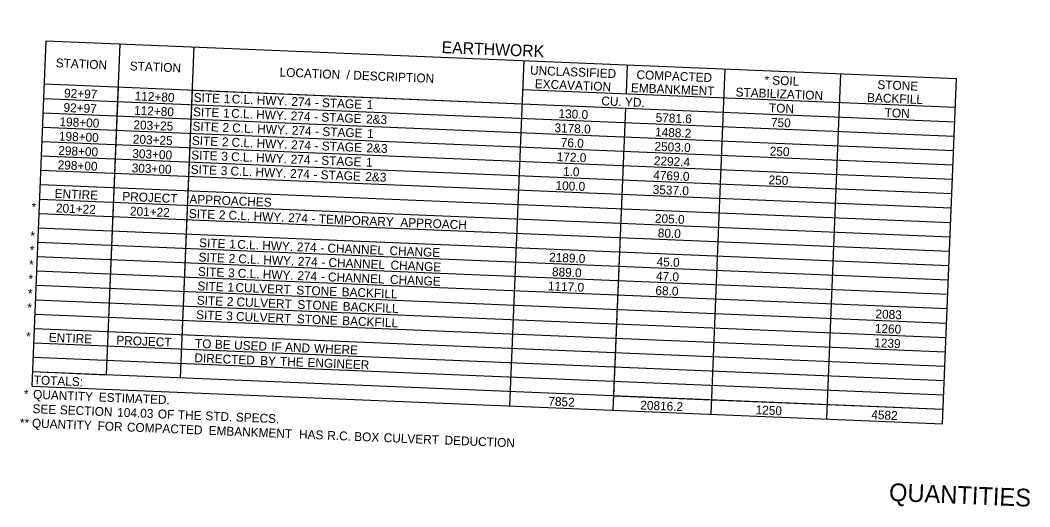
# Model space of a CAD drawing. Extents: x 1164179 to 1171425, y 1655958 to 1657208.
# Drawn here: x 1166923 to 1167607, y 1656114 to 1656443 of the extents above; entities that cross this region are included whole.
import ezdxf

# ---------------------------------------------------------------- set-up
doc = ezdxf.new("R2010")
doc.units = 0
doc.layers.add('Default', color=7, linetype='Continuous')
doc.layers.add('R_Border Prem', color=7, linetype='Continuous')

msp = doc.modelspace()

# ---------------------------------------------------------------- linework, layer by layer
at = {"layer": 'Default'}
for p, q in [((1166933.3, 1656443.19), (1166933.3, 1656443.19)), ((1166930.85, 1656195.43), (1166940.52, 1656429.23)), ((1166930.85, 1656195.43), (1166940.52, 1656429.23)), ((1166940.52, 1656429.23), (1167557.66, 1656403.7)), ((1166981.43, 1656203.09), (1166990.69, 1656427.15)), ((1167031.59, 1656201.02), (1167040.86, 1656425.08)), ((1167254.76, 1656182.03), (1167264.43, 1656415.83)), ((1167333.77, 1656393.44), (1167334.57, 1656412.93)), ((1167391.15, 1656176.39), (1167400.82, 1656410.19)), ((1167469.57, 1656173.14), (1167479.24, 1656406.94)), ((1166939.32, 1656400), (1167333.37, 1656383.7)), ((1167547.99, 1656169.9), (1167557.66, 1656403.7)), ((1166981.43, 1656203.09), (1166989.49, 1656397.93)), ((1167031.59, 1656201.02), (1167039.65, 1656395.85)), ((1167039.65, 1656395.85), (1167263.23, 1656386.6)), ((1167263.63, 1656396.34), (1167556.85, 1656384.21)), ((1166938.91, 1656390.26), (1167556.05, 1656364.73)), ((1167263.23, 1656386.6), (1167556.45, 1656374.47)), ((1166938.51, 1656380.52), (1167555.64, 1656354.99)), ((1167324.9, 1656179.13), (1167333.37, 1656383.7)), ((1167325.31, 1656188.87), (1167333.37, 1656383.7)), ((1166938.11, 1656370.78), (1167555.24, 1656345.25)), ((1166937.7, 1656361.04), (1167554.84, 1656335.51)), ((1166937.3, 1656351.29), (1167554.44, 1656325.76)), ((1166936.9, 1656341.55), (1167554.03, 1656316.02)), ((1166936.49, 1656331.81), (1167553.63, 1656306.28)), ((1166936.09, 1656322.07), (1167553.23, 1656296.54)), ((1166935.69, 1656312.33), (1167552.82, 1656286.8)), ((1166935.29, 1656302.59), (1167552.42, 1656277.06)), ((1166934.88, 1656292.84), (1167552.02, 1656267.31)), ((1166934.48, 1656283.1), (1167551.61, 1656257.57)), ((1166934.08, 1656273.36), (1167551.21, 1656247.83)), ((1166933.67, 1656263.62), (1167550.81, 1656238.09)), ((1166933.27, 1656253.88), (1167550.41, 1656228.35)), ((1166932.87, 1656244.14), (1167550, 1656218.61)), ((1166932.46, 1656234.39), (1167549.6, 1656208.86)), ((1166932.06, 1656224.65), (1167549.2, 1656199.12)), ((1166931.66, 1656214.91), (1167548.79, 1656189.38)), ((1166931.26, 1656205.17), (1166981.43, 1656203.09)), ((1166931.26, 1656205.17), (1167548.39, 1656179.64)), ((1166930.85, 1656195.43), (1167547.99, 1656169.9)), ((1167325.31, 1656188.87), (1167391.55, 1656186.13)), ((1167391.55, 1656186.13), (1167548.39, 1656179.64))]:
    msp.add_line(p, q, dxfattribs=at)

# ---------------------------------------------------------------- texts
for s, height, p in [('EARTHWORK', 8, (1167208.4, 1656420.97)), ('STATION', 6, (1166946.83, 1656411.33)), ('STATION', 6, (1166997, 1656409.25)), ('LOCATION', 6, (1167098.6, 1656405.05)), (' /', 6, (1167141.67, 1656403.27)), (' DESCRIPTION', 6, (1167146.33, 1656403.07)), ('UNCLASSIFIED', 6, (1167268.38, 1656406.36)), ('COMPACTED', 6, (1167340.53, 1656403.37)), ('EXCAVATION', 6, (1167271.62, 1656397.21)), ('EMBANKMENT', 6, (1167336.78, 1656394.52)), ('*', 6, (1167427.29, 1656399.78)), (' SOIL', 6, (1167430.37, 1656399.66)), ('STONE', 6, (1167503.84, 1656396.62)), ('92+97', 6, (1166952.48, 1656390.9)), ('112+80', 6, (1167000.33, 1656388.92)), ('SITE', 6, (1167040.3, 1656387.94)), ('STABILIZATION', 6, (1167407.73, 1656391.58)), ('BACKFILL', 6, (1167496.88, 1656387.9)), ('92+97', 6, (1166952.08, 1656381.16)), (' 1', 6, (1167058.48, 1656387.19)), (' C.L.', 6, (1167063.92, 1656386.97)), (' HWY.', 6, (1167080.87, 1656386.26)), (' 274', 6, (1167104.33, 1656385.29)), (' -', 6, (1167120.22, 1656384.64)), (' STAGE', 6, (1167125.07, 1656384.44)), (' 1', 6, (1167155.35, 1656383.18)), ('CU.', 6, (1167316.69, 1656385.59)), (' YD.', 6, (1167330.54, 1656385.02)), ('TON', 6, (1167430.36, 1656380.89)), ('112+80', 6, (1166999.93, 1656379.18)), ('SITE', 6, (1167039.9, 1656378.2)), (' 1', 6, (1167058.07, 1656377.45)), (' C.L.', 6, (1167063.51, 1656377.22)), (' HWY.', 6, (1167080.47, 1656376.52)), (' 274', 6, (1167103.93, 1656375.55)), (' STAGE', 6, (1167124.67, 1656374.69)), (' 2&3', 6, (1167154.95, 1656373.44)), ('130.0', 6, (1167287.67, 1656377.03)), ('5781.6', 6, (1167353.52, 1656374.31)), ('TON', 6, (1167508.78, 1656377.65)), ('198+00', 6, (1166949.36, 1656371.51)), ('203+25', 6, (1166999.49, 1656369.44)), ('SITE', 6, (1167039.5, 1656368.46)), (' 2', 6, (1167057.67, 1656367.71)), (' C.L.', 6, (1167064.21, 1656367.44)), (' HWY.', 6, (1167081.16, 1656366.74)), (' -', 6, (1167119.82, 1656374.9)), ('3178.0', 6, (1167284.94, 1656367.39)), ('750', 6, (1167431.68, 1656371.08)), ('198+00', 6, (1166948.95, 1656361.77)), ('203+25', 6, (1166999.09, 1656359.7)), (' 274', 6, (1167104.62, 1656365.77)), (' -', 6, (1167120.51, 1656365.11)), (' STAGE', 6, (1167125.36, 1656364.91)), (' 1', 6, (1167155.64, 1656363.65)), ('1488.2', 6, (1167353.15, 1656364.57)), ('SITE', 6, (1167039.09, 1656358.72)), (' 2', 6, (1167057.27, 1656357.97)), (' C.L.', 6, (1167063.8, 1656357.7)), (' HWY.', 6, (1167080.76, 1656356.99)), (' 274', 6, (1167104.22, 1656356.02)), (' STAGE', 6, (1167124.96, 1656355.17)), (' 2&3', 6, (1167155.24, 1656353.91)), ('76.0', 6, (1167289.19, 1656357.45)), ('2503.0', 6, (1167352.73, 1656354.83)), ('298+00', 6, (1166948.55, 1656352.03)), ('303+00', 6, (1166998.72, 1656349.95)), ('SITE', 6, (1167038.69, 1656348.98)), (' 3', 6, (1167056.86, 1656348.22)), (' C.L.', 6, (1167063.47, 1656347.95)), (' HWY.', 6, (1167080.42, 1656347.25)), (' 274', 6, (1167103.88, 1656346.28)), (' -', 6, (1167120.11, 1656355.37)), ('172.0', 6, (1167286.46, 1656347.81)), ('250', 6, (1167430.88, 1656351.59)), ('298+00', 6, (1166948.15, 1656342.29)), ('303+00', 6, (1166998.32, 1656340.21)), ('SITE', 6, (1167038.29, 1656339.23)), (' -', 6, (1167119.77, 1656345.62)), (' STAGE', 6, (1167124.62, 1656345.42)), (' 1', 6, (1167154.9, 1656344.17)), ('2292.4', 6, (1167352.33, 1656345.08)), (' 3', 6, (1167056.46, 1656338.48)), (' C.L.', 6, (1167063.06, 1656338.21)), (' HWY.', 6, (1167080.01, 1656337.51)), (' 274', 6, (1167103.48, 1656336.54)), (' -', 6, (1167119.37, 1656335.88)), (' STAGE', 6, (1167124.22, 1656335.68)), (' 2&3', 6, (1167154.49, 1656334.43)), ('1.0', 6, (1167290.71, 1656337.87)), ('4769.0', 6, (1167351.92, 1656335.34)), ('100.0', 6, (1167285.65, 1656328.33)), ('3537.0', 6, (1167351.52, 1656325.6)), ('250', 6, (1167430.07, 1656332.11)), ('ENTIRE', 6, (1166946.09, 1656322.86)), ('PROJECT', 6, (1166991.93, 1656320.96)), ('APPROACHES', 6, (1167037.45, 1656319.08)), ('*', 6, (1166930.36, 1656313.75)), ('201+22', 6, (1166946.96, 1656313.06)), ('201+22', 6, (1166997.13, 1656310.99)), ('SITE', 6, (1167037.05, 1656309.33)), (' 2', 6, (1167055.22, 1656308.58)), (' C.L.', 6, (1167061.76, 1656308.31)), (' HWY.', 6, (1167078.71, 1656307.61)), (' 274', 6, (1167102.18, 1656306.64)), (' TEMPORARY', 6, (1167122.92, 1656305.78)), ('205.0', 6, (1167353.04, 1656306.02)), (' -', 6, (1167118.06, 1656305.98)), (' APPROACH', 6, (1167178.24, 1656303.49)), ('*', 6, (1166929.55, 1656294.27)), ('80.0', 6, (1167354.96, 1656296.18)), ('*', 6, (1166929.15, 1656284.52)), ('SITE', 6, (1167044.04, 1656289.53)), (' 1', 6, (1167062.21, 1656288.78)), (' C.L.', 6, (1167067.65, 1656288.55)), (' HWY.', 6, (1167084.6, 1656287.85)), (' 274', 6, (1167108.07, 1656286.88)), (' CHANNEL', 6, (1167128.81, 1656286.02)), ('SITE', 6, (1167043.64, 1656279.79)), (' 2', 6, (1167061.81, 1656279.04)), (' C.L.', 6, (1167068.35, 1656278.77)), (' HWY.', 6, (1167085.3, 1656278.06)), (' -', 6, (1167123.96, 1656286.22)), (' CHANGE', 6, (1167170.87, 1656284.28)), ('2189.0', 6, (1167281.31, 1656279.71)), ('*', 6, (1166928.75, 1656274.78)), (' 274', 6, (1167108.76, 1656277.09)), (' -', 6, (1167124.65, 1656276.44)), (' CHANNEL', 6, (1167129.5, 1656276.24)), (' CHANGE', 6, (1167171.56, 1656274.5)), ('45.0', 6, (1167354.16, 1656276.7)), ('*', 6, (1166928.34, 1656265.04)), ('SITE', 6, (1167043.23, 1656270.05)), (' 3', 6, (1167061.4, 1656269.29)), (' C.L.', 6, (1167068.01, 1656269.02)), (' HWY.', 6, (1167084.96, 1656268.32)), (' 274', 6, (1167108.42, 1656267.35)), (' CHANNEL', 6, (1167129.16, 1656266.49)), (' CHANGE', 6, (1167171.22, 1656264.75)), ('889.0', 6, (1167283.24, 1656269.88)), ('47.0', 6, (1167353.76, 1656266.96)), ('SITE', 6, (1167042.83, 1656260.3)), (' 1', 6, (1167061, 1656259.55)), (' CULVERT', 6, (1167066.44, 1656259.33)), (' STONE', 6, (1167107.7, 1656257.62)), (' -', 6, (1167124.31, 1656266.69)), ('1117.0', 6, (1167280.5, 1656260.23)), ('68.0', 6, (1167353.35, 1656257.22)), ('*', 6, (1166927.94, 1656255.3)), ('SITE', 6, (1167042.43, 1656250.56)), (' BACKFILL', 6, (1167138.44, 1656256.35)), ('*', 6, (1166927.54, 1656245.56)), (' 2', 6, (1167060.6, 1656249.81)), (' CULVERT', 6, (1167067.14, 1656249.54)), (' STONE', 6, (1167108.39, 1656247.83)), (' BACKFILL', 6, (1167139.13, 1656246.56)), ('SITE', 6, (1167042.02, 1656240.82)), (' 3', 6, (1167060.2, 1656240.07)), (' CULVERT', 6, (1167066.8, 1656239.8)), (' STONE', 6, (1167108.05, 1656238.09)), (' BACKFILL', 6, (1167138.79, 1656236.82)), ('2083', 6, (1167502.53, 1656241.29)), ('1260', 6, (1167502.13, 1656231.55)), ('*', 6, (1166926.73, 1656226.07)), ('ENTIRE', 6, (1166942.06, 1656225.44)), ('PROJECT', 6, (1166987.9, 1656223.54)), ('TO', 6, (1167041.22, 1656221.34)), (' BE', 6, (1167052.48, 1656220.87)), (' USED', 6, (1167065.53, 1656220.33)), (' IF', 6, (1167090.68, 1656219.29)), (' AND', 6, (1167100.07, 1656218.9)), (' WHERE', 6, (1167119.64, 1656218.09)), ('1239', 6, (1167501.71, 1656221.8)), ('DIRECTED', 6, (1167040.81, 1656211.6)), (' BY', 6, (1167083.19, 1656209.84)), (' THE', 6, (1167096.62, 1656209.29)), (' ENGINEER', 6, (1167115.26, 1656208.52)), ('TOTALS:', 6, (1166931.88, 1656196.59)), ('*', 6, (1166925.12, 1656187.11)), ('QUANTITY', 6, (1166931.47, 1656186.84)), (' ESTIMATED.', 6, (1166973.76, 1656185.09)), ('7852', 6, (1167280.78, 1656182.15)), ('SEE', 6, (1166931.07, 1656177.1)), (' SECTION', 6, (1166947.39, 1656176.43)), ('20816.2', 6, (1167343.15, 1656179.57)), ('1250', 6, (1167421.3, 1656176.34)), (' 104.03', 6, (1166986.26, 1656174.82)), (' OF', 6, (1167013.82, 1656173.68)), (' THE', 6, (1167027.39, 1656173.12)), (' STD.', 6, (1167046.02, 1656172.35)), (' SPECS.', 6, (1167066.7, 1656171.49)), ('4582', 6, (1167499.72, 1656173.09)), ('**', 6, (1166922.5, 1656167.7)), ('QUANTITY', 6, (1166930.67, 1656167.36)), (' FOR', 6, (1166972.96, 1656165.61)), (' COMPACTED', 6, (1166992.85, 1656164.79)), (' EMBANKMENT', 6, (1167048.25, 1656162.5)), (' HAS', 6, (1167109.52, 1656159.96)), (' R.C.', 6, (1167128.64, 1656159.17)), (' BOX', 6, (1167146.98, 1656158.41)), (' CULVERT', 6, (1167166.94, 1656157.59)), (' DEDUCTION', 6, (1167208.2, 1656155.88))]:
    msp.add_text(s, height=height, rotation=357.63112, dxfattribs=at).set_placement(p)
at = {"layer": 'R_Border Prem'}
msp.add_text('QUANTITIES', height=12, rotation=357.63112, dxfattribs=at).set_placement((1167511.64, 1656117.65))

doc.saveas('drawing.dxf')
